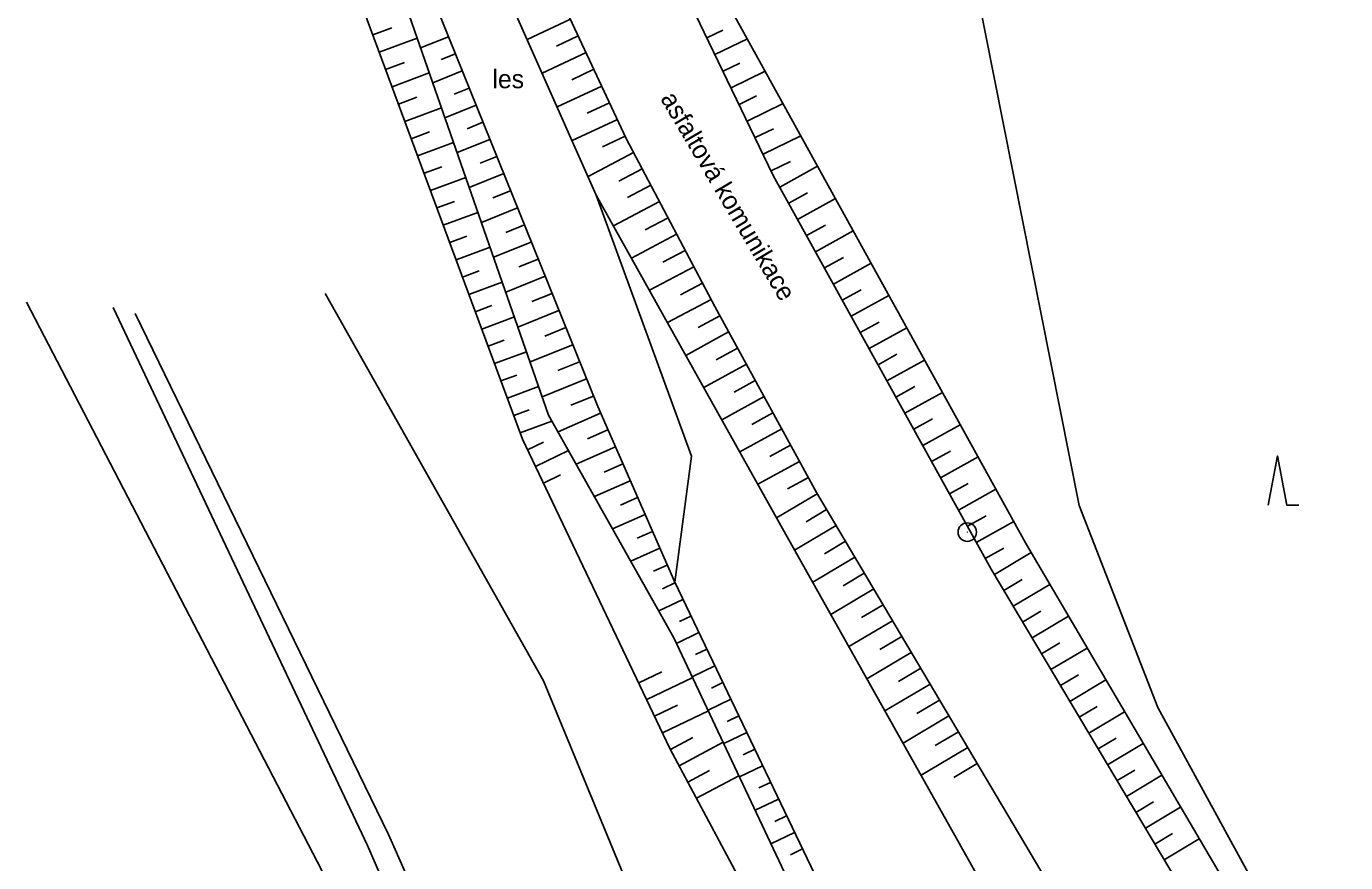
# Model space of a CAD drawing. Extents: x -762483 to -761175, y -1154655 to -1152452.
# Drawn here: x -761533.2 to -761479.5, y -1153611.2 to -1153577.2 of the extents above; entities that cross this region are included whole.
import ezdxf

# ---------------------------------------------------------------- set-up
doc = ezdxf.new("R2010")
doc.units = 0
for name, color, linetype in [('MAP_ZN_BP', 7, 'Continuous'), ('POMOC_POPIS', 7, 'Continuous'), ('ROZHRANÍ_PLOCH', 7, 'Continuous'), ('VÝŠKOPIS', 7, 'Continuous'), ('ZELEŇ', 7, 'Continuous'), ('ZN_KULTUR', 7, 'Continuous')]:
    doc.layers.add(name, color=color, linetype=linetype)

msp = doc.modelspace()

# ---------------------------------------------------------------- linework, layer by layer
at = {"layer": 'MAP_ZN_BP'}
for radius in [0.375, 0.0005]:
    msp.add_circle((-761494.89, -1153597.791), radius, dxfattribs=at)
at = {"layer": 'ROZHRANÍ_PLOCH'}
for points in [[(-761473.21, -1153684.07), (-761469.46, -1153679.5), (-761466.97, -1153675.46), (-761465.27, -1153671.92), (-761464.53, -1153668.61), (-761464.73, -1153664.68), (-761466, -1153658.71), (-761468.55, -1153651.77), (-761473.7, -1153641.76), (-761483.81, -1153624.91), (-761489.13, -1153616.22), (-761501.02, -1153596.18), (-761505.16, -1153588.62), (-761508.76, -1153581.79), (-761515.86, -1153566.65), (-761518.43, -1153558.82), (-761520.62, -1153549.31), (-761520.92, -1153543.45), (-761519.67, -1153527.09), (-761518.4, -1153518.01), (-761514.9, -1153498.24), (-761512.46, -1153485.54), (-761510.57, -1153476.01), (-761507.02, -1153459.49)], [(-761452.11, -1153680.09), (-761455.06, -1153677.36), (-761457.46, -1153672.86), (-761459.23, -1153668.13), (-761461.75, -1153656.48), (-761464.72, -1153649.83), (-761470.08, -1153639.37), (-761481.24, -1153620.57), (-761493.92, -1153599.29), (-761502.78, -1153583.29), (-761511.19, -1153565.87), (-761514.81, -1153554.8), (-761515.74, -1153549.15), (-761516.42, -1153543.11), (-761515.79, -1153528.81), (-761514.01, -1153518.23), (-761510.25, -1153496.92), (-761507.85, -1153485.44), (-761506.02, -1153476.2), (-761502.85, -1153460.41)], [(-761494.27, -1153676.22), (-761495.46, -1153669.67), (-761504.74, -1153646.67), (-761515.49, -1153624.01), (-761521.16, -1153611.52), (-761533.16, -1153588.45)], [(-761473.21, -1153684.07), (-761489.13, -1153679.95), (-761491.46, -1153676.53), (-761493.05, -1153668.86), (-761503.94, -1153642.37), (-761514.11, -1153622.46), (-761519.29, -1153610.52), (-761529.63, -1153588.66)]]:
    msp.add_lwpolyline(points, dxfattribs=at)
at = {"layer": 'VÝŠKOPIS'}
for p, q in [((-761511.033, -1153576.943), (-761512.79, -1153577.767)), ((-761519.07, -1153577.579), (-761518.29, -1153577.291)), ((-761518.809, -1153578.283), (-761517.264, -1153577.71)), ((-761515.991, -1153577.656), (-761517.123, -1153578.113)), ((-761510.714, -1153577.622), (-761511.6, -1153578.038)), ((-761505.476, -1153577.706), (-761504.835, -1153577.396)), ((-761505.15, -1153578.381), (-761503.83, -1153577.744)), ((-761518.548, -1153578.986), (-761517.782, -1153578.702)), ((-761515.71, -1153578.352), (-761516.293, -1153578.587)), ((-761510.396, -1153578.301), (-761512.181, -1153579.138)), ((-761504.824, -1153579.057), (-761504.146, -1153578.729)), ((-761518.288, -1153579.689), (-761516.77, -1153579.127)), ((-761515.429, -1153579.047), (-761516.628, -1153579.531)), ((-761510.078, -1153578.98), (-761510.977, -1153579.402)), ((-761504.498, -1153579.732), (-761503.104, -1153579.059)), ((-761515.148, -1153579.742), (-761515.765, -1153579.991)), ((-761509.759, -1153579.659), (-761511.572, -1153580.509)), ((-761518.027, -1153580.392), (-761517.275, -1153580.114)), ((-761509.441, -1153580.338), (-761510.354, -1153580.767)), ((-761504.172, -1153580.408), (-761503.456, -1153580.062)), ((-761503.846, -1153581.083), (-761502.378, -1153580.375)), ((-761517.766, -1153581.096), (-761516.275, -1153580.543)), ((-761514.867, -1153580.438), (-761516.134, -1153580.949)), ((-761514.587, -1153581.133), (-761515.237, -1153581.396)), ((-761509.122, -1153581.018), (-761510.962, -1153581.88)), ((-761503.519, -1153581.758), (-761502.767, -1153581.395)), ((-761517.506, -1153581.799), (-761516.767, -1153581.525)), ((-761517.245, -1153582.502), (-761515.781, -1153581.96)), ((-761514.306, -1153581.829), (-761515.639, -1153582.367)), ((-761508.804, -1153581.697), (-761509.731, -1153582.131)), ((-761503.193, -1153582.434), (-761501.652, -1153581.69)), ((-761514.025, -1153582.524), (-761514.708, -1153582.8)), ((-761508.458, -1153582.362), (-761510.313, -1153583.34)), ((-761516.984, -1153583.205), (-761516.259, -1153582.937)), ((-761508.109, -1153583.026), (-761509.058, -1153583.526)), ((-761502.867, -1153583.109), (-761502.078, -1153582.728)), ((-761502.514, -1153583.77), (-761500.974, -1153582.918)), ((-761516.724, -1153583.909), (-761515.287, -1153583.376)), ((-761513.744, -1153583.22), (-761515.145, -1153583.785)), ((-761513.463, -1153583.915), (-761514.18, -1153584.205)), ((-761507.759, -1153583.689), (-761508.703, -1153584.187)), ((-761502.151, -1153584.427), (-761501.381, -1153584)), ((-761516.463, -1153584.612), (-761515.752, -1153584.348)), ((-761513.182, -1153584.611), (-761514.65, -1153585.203)), ((-761507.409, -1153584.353), (-761509.281, -1153585.339)), ((-761501.787, -1153585.083), (-761500.249, -1153584.231)), ((-761516.203, -1153585.315), (-761514.793, -1153584.793)), ((-761507.06, -1153585.016), (-761507.987, -1153585.505)), ((-761515.942, -1153586.018), (-761515.244, -1153585.76)), ((-761512.902, -1153585.306), (-761513.652, -1153585.609)), ((-761506.71, -1153585.68), (-761508.549, -1153586.649)), ((-761501.424, -1153585.739), (-761500.655, -1153585.313)), ((-761501.061, -1153586.395), (-761499.524, -1153585.544)), ((-761515.681, -1153586.722), (-761514.299, -1153586.209)), ((-761512.621, -1153586.001), (-761514.155, -1153586.621)), ((-761512.34, -1153586.697), (-761513.124, -1153587.014)), ((-761506.36, -1153586.343), (-761507.271, -1153586.823)), ((-761500.697, -1153587.051), (-761499.929, -1153586.626)), ((-761515.421, -1153587.425), (-761514.736, -1153587.171)), ((-761506.01, -1153587.007), (-761507.817, -1153587.959)), ((-761500.334, -1153587.707), (-761498.799, -1153586.857)), ((-761515.16, -1153588.128), (-761513.805, -1153587.626)), ((-761512.059, -1153587.392), (-761513.661, -1153588.039)), ((-761505.661, -1153587.67), (-761506.556, -1153588.142)), ((-761511.778, -1153588.088), (-761512.596, -1153588.418)), ((-761505.311, -1153588.333), (-761507.084, -1153589.268)), ((-761499.971, -1153588.363), (-761499.204, -1153587.939)), ((-761499.607, -1153589.019), (-761498.074, -1153588.17)), ((-761514.899, -1153588.831), (-761514.229, -1153588.583)), ((-761511.498, -1153588.783), (-761513.166, -1153589.457)), ((-761504.955, -1153588.994), (-761505.829, -1153589.472)), ((-761514.639, -1153589.535), (-761513.311, -1153589.043)), ((-761511.217, -1153589.479), (-761512.068, -1153589.822)), ((-761499.244, -1153589.676), (-761498.478, -1153589.251)), ((-761498.881, -1153590.332), (-761497.349, -1153589.483)), ((-761514.378, -1153590.238), (-761513.721, -1153589.994)), ((-761504.595, -1153589.652), (-761506.337, -1153590.605)), ((-761514.117, -1153590.941), (-761512.817, -1153590.459)), ((-761510.936, -1153590.174), (-761512.672, -1153590.875)), ((-761504.235, -1153590.309), (-761505.103, -1153590.785)), ((-761498.517, -1153590.988), (-761497.752, -1153590.564)), ((-761510.655, -1153590.87), (-761511.54, -1153591.227)), ((-761503.875, -1153590.967), (-761505.604, -1153591.914)), ((-761498.154, -1153591.644), (-761496.624, -1153590.797)), ((-761513.857, -1153591.644), (-761513.213, -1153591.406)), ((-761510.374, -1153591.565), (-761512.177, -1153592.293)), ((-761503.514, -1153591.625), (-761504.376, -1153592.097)), ((-761513.596, -1153592.348), (-761512.323, -1153591.876)), ((-761497.791, -1153592.3), (-761497.026, -1153591.877)), ((-761497.427, -1153592.956), (-761495.899, -1153592.11)), ((-761510.093, -1153592.26), (-761511.012, -1153592.631)), ((-761503.154, -1153592.283), (-761504.872, -1153593.224)), ((-761513.335, -1153593.051), (-761512.706, -1153592.817)), ((-761513.075, -1153593.754), (-761511.782, -1153593.275)), ((-761509.805, -1153592.953), (-761511.535, -1153593.712)), ((-761502.794, -1153592.941), (-761503.65, -1153593.41)), ((-761497.064, -1153593.612), (-761496.3, -1153593.189)), ((-761509.503, -1153593.639), (-761510.334, -1153594.004)), ((-761502.434, -1153593.598), (-761504.14, -1153594.533)), ((-761496.701, -1153594.268), (-761495.174, -1153593.423)), ((-761512.774, -1153594.441), (-761512.125, -1153594.13)), ((-761509.202, -1153594.326), (-761510.795, -1153595.026)), ((-761502.073, -1153594.256), (-761502.924, -1153594.722)), ((-761512.451, -1153595.118), (-761511.106, -1153594.475)), ((-761496.337, -1153594.924), (-761495.574, -1153594.502)), ((-761495.974, -1153595.581), (-761494.449, -1153594.736)), ((-761508.9, -1153595.013), (-761509.663, -1153595.348)), ((-761501.713, -1153594.914), (-761503.408, -1153595.842)), ((-761512.128, -1153595.794), (-761511.432, -1153595.462)), ((-761508.599, -1153595.7), (-761510.055, -1153596.339)), ((-761501.353, -1153595.572), (-761502.197, -1153596.034)), ((-761495.611, -1153596.237), (-761494.849, -1153595.815)), ((-761508.297, -1153596.386), (-761508.991, -1153596.691)), ((-761500.991, -1153596.229), (-761502.644, -1153597.209)), ((-761495.247, -1153596.893), (-761493.724, -1153596.049)), ((-761500.608, -1153596.874), (-761501.443, -1153597.369)), ((-761507.996, -1153597.073), (-761509.315, -1153597.652)), ((-761500.226, -1153597.519), (-761501.91, -1153598.518)), ((-761494.884, -1153597.549), (-761494.123, -1153597.127)), ((-761494.521, -1153598.205), (-761492.999, -1153597.362)), ((-761507.694, -1153597.76), (-761508.32, -1153598.034)), ((-761507.393, -1153598.447), (-761508.575, -1153598.965)), ((-761499.843, -1153598.164), (-761500.693, -1153598.668)), ((-761494.157, -1153598.861), (-761493.397, -1153598.44)), ((-761493.787, -1153599.513), (-761492.29, -1153598.621)), ((-761507.091, -1153599.133), (-761507.648, -1153599.378)), ((-761499.46, -1153598.809), (-761501.175, -1153599.826)), ((-761499.078, -1153599.454), (-761499.942, -1153599.967)), ((-761493.403, -1153600.158), (-761492.657, -1153599.713)), ((-761506.777, -1153599.846), (-761507.29, -1153600.092)), ((-761498.695, -1153600.099), (-761500.44, -1153601.134)), ((-761493.019, -1153600.802), (-761491.53, -1153599.914)), ((-761506.453, -1153600.523), (-761507.433, -1153600.992)), ((-761498.312, -1153600.744), (-761499.192, -1153601.266)), ((-761506.129, -1153601.199), (-761506.596, -1153601.423)), ((-761492.635, -1153601.446), (-761491.893, -1153601.004)), ((-761492.251, -1153602.09), (-761490.77, -1153601.208)), ((-761497.929, -1153601.389), (-761499.705, -1153602.442)), ((-761505.805, -1153601.875), (-761506.712, -1153602.31)), ((-761497.547, -1153602.034), (-761498.442, -1153602.565)), ((-761491.867, -1153602.735), (-761491.129, -1153602.294)), ((-761505.481, -1153602.552), (-761505.936, -1153602.77)), ((-761497.164, -1153602.679), (-761498.97, -1153603.75)), ((-761491.484, -1153603.379), (-761490.01, -1153602.501)), ((-761508.251, -1153603.917), (-761507.314, -1153603.469)), ((-761505.156, -1153603.228), (-761506.072, -1153603.667)), ((-761496.781, -1153603.324), (-761497.692, -1153603.864)), ((-761507.928, -1153604.593), (-761506.057, -1153603.7)), ((-761504.832, -1153603.904), (-761505.293, -1153604.125)), ((-761496.399, -1153603.969), (-761498.235, -1153605.058)), ((-761491.1, -1153604.023), (-761490.365, -1153603.585)), ((-761490.716, -1153604.668), (-761489.25, -1153603.794)), ((-761507.605, -1153605.27), (-761506.671, -1153604.824)), ((-761507.282, -1153605.947), (-761505.418, -1153605.057)), ((-761504.508, -1153604.581), (-761505.433, -1153605.024)), ((-761496.016, -1153604.614), (-761496.942, -1153605.163)), ((-761490.332, -1153605.312), (-761489.601, -1153604.876)), ((-761489.948, -1153605.956), (-761488.49, -1153605.087)), ((-761504.184, -1153605.257), (-761504.649, -1153605.48)), ((-761495.633, -1153605.259), (-761497.5, -1153606.366)), ((-761506.957, -1153606.623), (-761506.047, -1153606.137)), ((-761503.86, -1153605.933), (-761504.794, -1153606.381)), ((-761495.251, -1153605.904), (-761496.191, -1153606.462)), ((-761489.564, -1153606.6), (-761488.837, -1153606.167)), ((-761506.604, -1153607.284), (-761504.818, -1153606.33)), ((-761503.536, -1153606.61), (-761504.005, -1153606.835)), ((-761494.868, -1153606.549), (-761496.765, -1153607.674)), ((-761489.18, -1153607.245), (-761487.73, -1153606.38)), ((-761494.485, -1153607.194), (-761495.441, -1153607.761)), ((-761506.25, -1153607.946), (-761505.374, -1153607.478)), ((-761505.897, -1153608.607), (-761504.178, -1153607.689)), ((-761503.211, -1153607.286), (-761504.155, -1153607.738)), ((-761488.796, -1153607.889), (-761488.073, -1153607.458)), ((-761488.412, -1153608.533), (-761486.97, -1153607.674)), ((-761502.887, -1153607.962), (-761503.361, -1153608.189)), ((-761502.563, -1153608.639), (-761503.515, -1153609.095)), ((-761488.028, -1153609.178), (-761487.309, -1153608.749)), ((-761502.239, -1153609.315), (-761502.717, -1153609.544)), ((-761487.644, -1153609.822), (-761486.209, -1153608.967)), ((-761501.915, -1153609.991), (-761502.876, -1153610.452)), ((-761487.261, -1153610.466), (-761486.545, -1153610.04)), ((-761486.877, -1153611.11), (-761485.449, -1153610.26)), ((-761501.591, -1153610.668), (-761502.074, -1153610.899))]:
    msp.add_line(p, q, dxfattribs=at)
for points in [[(-761472.39, -1153633.33), (-761479.86, -1153619.77), (-761492.52, -1153598.23), (-761505.34, -1153575.01), (-761509.58, -1153565.6), (-761513.83, -1153553.93), (-761514.33, -1153548.93), (-761514.54, -1153543.35), (-761514.65, -1153531.04), (-761510.51, -1153505.03)], [(-761479.87, -1153657.21), (-761481.77, -1153653.84), (-761499.98, -1153616.6), (-761506.82, -1153602.08), (-761511.92, -1153593.03), (-761519.06, -1153572.56), (-761524.81, -1153556.17), (-761528.16, -1153544.33)], [(-761474.97, -1153672.67), (-761481.14, -1153657.53), (-761482.71, -1153655.62), (-761499.8, -1153620.02), (-761506.98, -1153606.58), (-761512.98, -1153594.01), (-761520.93, -1153572.56), (-761525.32, -1153558.87), (-761528.36, -1153547.72)], [(-761485.37, -1153626.75), (-761491.12, -1153617.72), (-761502.33, -1153597.77), (-761509.98, -1153584.09)], [(-761479.02, -1153657.23), (-761481.08, -1153653.46), (-761506.79, -1153599.82)]]:
    msp.add_lwpolyline(points, dxfattribs=at)
at = {"layer": 'ZELEŇ'}
for points in [[(-761472.39, -1153633.33), (-761479.21, -1153619.43), (-761487.13, -1153604.92), (-761490.34, -1153596.71), (-761495.72, -1153569.61), (-761500.02, -1153539.43), (-761507.72, -1153504.64)], [(-761509.98, -1153584.09), (-761517.59, -1153566.97), (-761520.18, -1153558.87), (-761522.43, -1153550.02), (-761523.2, -1153547.66), (-761523.22, -1153542.15)], [(-761506.79, -1153599.82), (-761509.92, -1153592.69), (-761518, -1153572.68), (-761523.87, -1153555.59), (-761526.98, -1153547.13)], [(-761509.98, -1153584.09), (-761506.11, -1153594.7), (-761506.79, -1153599.82)], [(-761500.1, -1153632.97), (-761512.12, -1153603.84), (-761521, -1153588.09)], [(-761492.87, -1153661.72), (-761492.96, -1153659.54), (-761501.51, -1153642.51), (-761512.01, -1153624.56), (-761518.43, -1153610.08), (-761528.74, -1153588.9)]]:
    msp.add_lwpolyline(points, dxfattribs=at)
at = {"layer": 'ZN_KULTUR'}
msp.add_lwpolyline([(-761482.645, -1153596.69), (-761482.27, -1153594.69), (-761481.895, -1153596.69), (-761481.395, -1153596.69)], dxfattribs=at)

# ---------------------------------------------------------------- texts
at = {"layer": 'POMOC_POPIS'}
msp.add_text('asfaltová komunikace', height=0.75, rotation=300.6658, dxfattribs=at).set_placement((-761507.39, -1153580.17))
at = {"layer": 'ZELEŇ'}
msp.add_text('les', height=0.75, dxfattribs=at).set_placement((-761514.2, -1153579.75))

doc.saveas('drawing.dxf')
